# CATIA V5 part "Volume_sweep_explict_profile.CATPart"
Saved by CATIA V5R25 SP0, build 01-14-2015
Part number: Part1
Bounding box of the stored display mesh (mm): x -27.367 to 27.367, y -27.367 to 38.532, z 0 to 133.822
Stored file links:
  E:\cadcim\GSD_cat_v5-6r2014\Part_files\Volume_sweep_explict_profile.CATPart
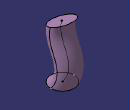
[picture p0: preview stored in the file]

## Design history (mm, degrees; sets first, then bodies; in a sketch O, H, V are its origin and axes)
Set1
  Sketch1 on xy-plane, origin (0, 0, 0), H (1, 0, 0), V (0, 1, 0)
    circle A1 centre (0, 0) radius 27.367
  Sketch2 on yz-plane, origin (0, 0, 0), H (0, 1, 0), V (0, 0, 1)
    spline S1 through (0, 0) (11.9407, 56.843) (-3.4307, 102.6672) (-1.4005, 123.8391)
    point P1 (0, 0)
    coincidence: P1 O
  Sweep1: type Unspec, Profile Sketch1, Guide Sketch2
Body1 (main body)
